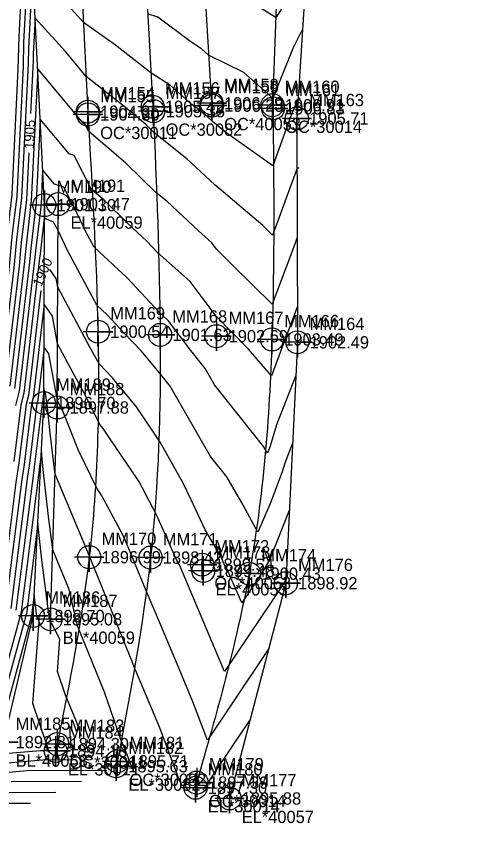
# Model space of a CAD drawing. Extents: x 1004378 to 1005103, y 553854 to 554288.
# Drawn here: x 1004990.4 to 1005086, y 553861.2 to 554030.8 of the extents above; entities that cross this region are included whole.
import ezdxf

# ---------------------------------------------------------------- set-up
doc = ezdxf.new("R2010")
doc.units = 0
for name, color, linetype in [('DTM Contours Major', 7, 'Continuous'), ('DTM Contours Major Text', 7, 'Continuous'), ('DTM Contours Minor', 7, 'Continuous'), ('Exist DTM Breakline', 7, 'Continuous'), ('Exist DTM Breakline Cogo Comment', 7, 'Continuous'), ('Exist DTM Breakline Cogo Elevation', 7, 'Continuous'), ('Exist DTM Breakline Cogo Number', 7, 'Continuous'), ('Exist DTM Breakline Cogo Point CELL', 7, 'Continuous'), ('Exist DTM Crownline', 7, 'Continuous'), ('Exist DTM Crownline Cogo Comment', 7, 'Continuous'), ('Exist DTM Crownline Cogo Elevation', 7, 'Continuous'), ('Exist DTM Crownline Cogo Number', 7, 'Continuous'), ('Exist DTM Crownline Cogo Point CELL', 7, 'Continuous'), ('Exist Roads EOP', 7, 'Continuous'), ('Exist Roads EOP Cogo Comment', 7, 'Continuous'), ('Exist Roads EOP Cogo Elevation', 7, 'Continuous'), ('Exist Roads EOP Cogo Number', 7, 'Continuous'), ('Exist Roads EOP Cogo Point CELL', 7, 'Continuous')]:
    doc.layers.add(name, color=color, linetype=linetype)

msp = doc.modelspace()

# ---------------------------------------------------------------- linework, layer by layer
at = {"layer": 'DTM Contours Major'}
for points in [[(1005047.91, 553999.99), (1005047.5, 554000.01), (1005043.02, 553987.76), (1005042.49, 553986.36), (1005040.56, 553988.28), (1005030.78, 553996.6), (1005025.09, 554001.89), (1005018.38, 554007.25), (1005016.77, 554008.82), (1005013.79, 554011.34), (1005013.15, 554011.88), (1005012.9, 554012.07), (1005004.57, 554018.62), (1005000.33, 554023.7), (1004994.19, 554030.53), (1004993.8, 554023.22), (1004993.77, 554021.82), (1004993.26, 554011.12)], [(1004992.87, 554003.13), (1004992.42, 553993.62), (1004991.37, 553984.88), (1004990.92, 553980.07), (1004988.11, 553956.08), (1004986.93, 553951.45), (1004985.68, 553941.48), (1004984.33, 553932.76), (1004981.8, 553912.85), (1004981.75, 553912.53), (1004979.52, 553904.17)], [(1005045.93, 553930.3), (1005041.91, 553920.21), (1005039.87, 553916.92), (1005036.26, 553911.52), (1005033.57, 553917.72), (1005033.17, 553918.35), (1005031.99, 553920.94), (1005028.82, 553926.38), (1005025.97, 553932.52), (1005024.26, 553936), (1005019.63, 553944.2), (1005014.83, 553951.43), (1005011.82, 553955.02), (1005009.84, 553957.4), (1005007.19, 553960.18), (1005005.29, 553963.57), (1004998.8, 553975.75), (1004998.47, 553977.56), (1004997.19, 553979.39)], [(1004995.34, 553975.11), (1004992.83, 553953.74), (1004992.37, 553951.9), (1004990.88, 553940), (1004990.26, 553936.01), (1004987.1, 553911.09), (1004987.07, 553910.91), (1004985.27, 553904.17), (1004980.32, 553886.22), (1004977.19, 553877.08)], [(1004998.72, 553897.59), (1004999.24, 553904.13), (1004997.1, 553908.23), (1004995.53, 553920.31), (1004994.71, 553927.66), (1004992.39, 553909.32), (1004992.38, 553909.29), (1004992.01, 553907.9), (1004985.46, 553884.12), (1004984.06, 553880.03), (1004983.56, 553878.58), (1004995.75, 553879.6), (1005002.27, 553879.64)], [(1005003.63, 553884.36), (1005002.66, 553887.17), (1005000.39, 553892.74), (1004998.72, 553897.59)]]:
    msp.add_lwpolyline(points, dxfattribs=at)
at = {"layer": 'DTM Contours Minor'}
for points in [[(1005048.17, 554014.12), (1005047.74, 554014.14), (1005046.29, 554010.74), (1005046.23, 554010.63), (1005042.56, 554000.44), (1005032.99, 554007.21), (1005030.3, 554009.5), (1005029.17, 554010.55), (1005026.87, 554012.38), (1005026.42, 554012.67), (1005026.07, 554012.93), (1005021.74, 554016.78), (1005017.73, 554019.38), (1005010.51, 554025), (1005004.02, 554029.64), (1004995.48, 554039.15)], [(1004991.39, 554037.31), (1004990.84, 554026.76), (1004990.69, 554020.12), (1004989.46, 553994.57), (1004988.51, 553986.65), (1004987.78, 553978.89), (1004985.27, 553957.48), (1004983.67, 553951.19), (1004982.57, 553942.36), (1004980.77, 553930.81), (1004978.63, 553913.91), (1004978.56, 553913.5), (1004974.48, 553898.21), (1004972.11, 553889.58), (1004965.54, 553870.4), (1004956.56, 553865.52), (1004952.9, 553863.53)], [(1004992.42, 554036.73), (1004991.83, 554025.58), (1004991.72, 554020.69), (1004990.45, 553994.25), (1004989.47, 553986.06), (1004988.82, 553979.28), (1004986.22, 553957.01), (1004984.76, 553951.28), (1004983.61, 553942.07), (1004981.96, 553931.46), (1004979.69, 553913.56), (1004979.63, 553913.17), (1004975.83, 553898.95), (1004973.13, 553889.16), (1004965.67, 553867.39), (1004961.09, 553864.9), (1004956.41, 553862.35)], [(1004993.44, 554036.15), (1004992.81, 554024.4), (1004992.74, 554021.25), (1004991.43, 553993.93), (1004990.42, 553985.47), (1004989.87, 553979.68), (1004987.16, 553956.55), (1004985.84, 553951.37), (1004984.64, 553941.77), (1004983.15, 553932.11), (1004980.75, 553913.21), (1004980.69, 553912.85), (1004977.18, 553899.7), (1004974.16, 553888.74), (1004965.81, 553864.38), (1004965.62, 553864.28), (1004959.92, 553861.18)], [(1005045.03, 554033.43), (1005043.18, 554030.65), (1005034.44, 554036.03)], [(1005048.63, 554028.24), (1005046.65, 554024.32), (1005042.56, 554014.24), (1005036.66, 554019.42), (1005029.51, 554022.98), (1005028.05, 554024.28), (1005025.89, 554025.68), (1005019.17, 554030.68), (1005017.07, 554031.39)], [(1005047.64, 553985.85), (1005047.53, 553985.86), (1005046.25, 553982.35), (1005042.43, 553972.28), (1005034.55, 553980.06), (1005031.13, 553983.52), (1005030.17, 553984.8), (1005027.47, 553987.22), (1005021.02, 553993.23), (1005018.75, 553995.04), (1005012.58, 554001.07), (1005005.09, 554007.41), (1005004.3, 554008.99), (1005004.05, 554009.07), (1004994.7, 554020.22), (1004993.4, 553993.3), (1004992.33, 553984.29), (1004991.96, 553980.46), (1004989.05, 553955.61)], [(1005047.56, 553971.71), (1005044.95, 553964.83), (1005042.27, 553957.75), (1005037.64, 553963.14), (1005031.01, 553969.84), (1005025.73, 553976.9), (1005019.12, 553982.83), (1005016.95, 553985.14), (1005013, 553988.81), (1005008.39, 553993.31), (1005005.63, 553995.64), (1005002.16, 554002.55), (1005001.09, 554002.9), (1004995.2, 554009.92), (1004994.39, 553992.98), (1004993.28, 553983.7), (1004993.01, 553980.86), (1004990, 553955.14)], [(1005047.25, 553957.77), (1005043.34, 553947.75), (1005042.05, 553943.43), (1005041.51, 553941.97), (1005040.74, 553943.31), (1005030.69, 553955.9), (1005028.77, 553959.24), (1005025.85, 553962.91), (1005021.29, 553969), (1005019.49, 553970.61), (1005012.89, 553977.64), (1005006.18, 553983.88), (1005004.42, 553987.16), (1005002.85, 553990.5), (1005000.02, 553996.1), (1004998.12, 553996.74), (1004995.71, 553999.61), (1004995.38, 553992.67), (1004994.23, 553983.11), (1004994.05, 553981.25), (1004990.94, 553954.67), (1004990.19, 553951.72)], [(1005046.59, 553944.03), (1005045, 553939.97), (1005044.48, 553938.21), (1005042.13, 553931.91), (1005039.54, 553925.94), (1005036.19, 553932.02), (1005033.22, 553937.19), (1005029.91, 553941.34), (1005021.69, 553955.63), (1005019.79, 553958.02), (1005015.86, 553962.72), (1005012.33, 553966.42), (1005008.83, 553970.14), (1005006.72, 553972.11), (1005000.77, 553983.24), (1004998.86, 553987.29), (1004997.91, 553989), (1004996.05, 553989.78), (1004995.18, 553982.52), (1004995.1, 553981.65), (1004991.89, 553954.21), (1004991.28, 553951.81), (1004989.84, 553940.3)], [(1005045.28, 553916.57), (1005044.99, 553915.86), (1005044.85, 553915.62), (1005032.75, 553897.54), (1005031.76, 553899.83), (1005025.62, 553914.47), (1005023.57, 553919.26), (1005023.12, 553919.99), (1005019.25, 553928.69), (1005018.99, 553929.26), (1005018.84, 553929.58), (1005015.27, 553936.32), (1005009.26, 553945.18), (1005008.05, 553947), (1005007.37, 553947.81), (1005004.37, 553953.85), (1005002.18, 553957.77), (1004998.75, 553964.22), (1004997.71, 553969.88), (1004996.01, 553972.31), (1004993.78, 553953.27), (1004993.45, 553951.99), (1004991.92, 553939.71), (1004991.44, 553936.66), (1004988.15, 553910.74)], [(1005041.74, 553902.23), (1005034.79, 553891.83), (1005029.24, 553883.56), (1005026.32, 553891.42), (1005023.5, 553898.08), (1005019.77, 553906.99), (1005016.63, 553914.3), (1005014.02, 553920.76), (1005012.14, 553925.08), (1005007.74, 553933.28), (1005007.44, 553933.84), (1005006.83, 553934.74), (1005003, 553942.51), (1004999.72, 553950.72), (1004999.31, 553951.56), (1004999.07, 553951.98), (1004998.7, 553952.68), (1004996.95, 553962.2), (1004995.99, 553963.57), (1004994.72, 553952.8), (1004994.54, 553952.08), (1004992.96, 553939.41), (1004992.63, 553937.3), (1004989.21, 553910.38)], [(1005023.94, 553874.7), (1005023.47, 553875.69), (1005023.36, 553875.95), (1005019.59, 553886.12), (1005014.13, 553899.01), (1005013.92, 553899.6), (1005013.73, 553900.09), (1005006.71, 553917.34), (1005005.31, 553920.82), (1005005.29, 553920.87), (1005005.22, 553921), (1005002.78, 553926.86), (1004998.26, 553937.74), (1004998.23, 553937.9), (1004998.21, 553938.13), (1004997.27, 553946.07), (1004996.66, 553951.96), (1004996.19, 553954.51), (1004995.96, 553954.83), (1004995.67, 553952.33), (1004995.63, 553952.16), (1004994, 553939.12), (1004993.82, 553937.95), (1004990.27, 553910.03)], [(1005014.22, 553877.33), (1005014.09, 553877.59), (1005013.7, 553878.53), (1005012.86, 553880.82), (1005011.63, 553883.71), (1005008.29, 553893.39), (1005005.05, 553901.35), (1005002.81, 553906.87), (1005001.11, 553914.27), (1004997.76, 553922.33), (1004996.88, 553929.11), (1004995.83, 553938.64), (1004995.65, 553940.13), (1004995.45, 553942.11), (1004995.03, 553938.82), (1004995, 553938.6), (1004991.33, 553909.68), (1004991.32, 553909.61), (1004990.66, 553907.15), (1004984.43, 553884.54), (1004982.39, 553878.59), (1004981.67, 553876.48), (1004992.54, 553877.39), (1005008.76, 553877.47)], [(1004996.93, 553881.65), (1004996.51, 553882.87), (1004993.7, 553891.03), (1004995.03, 553907.77), (1004994.53, 553908.72), (1004994.17, 553911.51), (1004993.98, 553913.22), (1004993.44, 553908.97), (1004993.44, 553908.96), (1004993.36, 553908.64), (1004986.49, 553883.7), (1004985.72, 553881.48), (1004985.45, 553880.68), (1004996.93, 553881.65)], [(1005037.97, 553887.83), (1005037.41, 553886.99), (1005035.67, 553884.41), (1005028.79, 553874.13), (1005028.29, 553873.45)], [(1004989.33, 553875.18), (1005003.59, 553875.25)], [(1004986.12, 553872.96), (1004998.41, 553873.03)], [(1005034.2, 553873.44), (1005033.23, 553871.99), (1005033.17, 553871.92)], [(1004982.91, 553870.75), (1004993.24, 553870.8)]]:
    msp.add_lwpolyline(points, dxfattribs=at)
at = {"layer": 'Exist DTM Breakline'}
for p, q in [((1005027.5, 554055.67), (1005030.12, 554013.17)), ((1005030.12, 554013.17), (1005030.18, 554012.7)), ((1005028.18, 553919.3), (1005028.42, 553918.04))]:
    msp.add_line(p, q, dxfattribs=at)
for points in [[(1005086.04, 554233.62), (1005066.81, 554200.26), (1005058.41, 554172.31), (1005052.46, 554140.65), (1005052.44, 554096.34), (1005050.24, 554053.66), (1005047.48, 554010.1), (1005047.57, 553964.54), (1005045.23, 553915.52), (1005033.75, 553871.73)], [(1004987.71, 553883.19), (1004993.76, 553908.86), (1004995.96, 553952.19), (1004996.06, 553992.45), (1004993.93, 554035.88), (1004994.31, 554070.39), (1004993.03, 554080.74), (1004990.27, 554106.2), (1004991.44, 554130.88), (1004994.66, 554165), (1004997.71, 554181.71), (1005005.11, 554206.99)], [(1004997.31, 553908.19), (1004998.69, 553951.28), (1004998.88, 553992.66)]]:
    msp.add_lwpolyline(points, dxfattribs=at)
at = {"layer": 'Exist DTM Breakline Cogo Point CELL'}
for points in [[(1005030.12, 554016.17), (1005030.12, 554010.17), (1005030.12, 554013.17), (1005033.12, 554013.17), (1005027.12, 554013.17)], [(1005030.18, 554015.7), (1005030.18, 554009.7), (1005030.18, 554012.7), (1005033.18, 554012.7), (1005027.18, 554012.7)], [(1005047.48, 554013.1), (1005047.48, 554007.1), (1005047.48, 554010.1), (1005050.48, 554010.1), (1005044.48, 554010.1)], [(1004996.06, 553995.45), (1004996.06, 553989.45), (1004996.06, 553992.45), (1004999.06, 553992.45), (1004993.06, 553992.45)], [(1004998.88, 553995.66), (1004998.88, 553989.66), (1004998.88, 553992.66), (1005001.88, 553992.66), (1004995.88, 553992.66)], [(1005031.08, 553968.79), (1005031.08, 553962.79), (1005031.08, 553965.79), (1005034.08, 553965.79), (1005028.08, 553965.79)], [(1005047.57, 553967.54), (1005047.57, 553961.54), (1005047.57, 553964.54), (1005050.57, 553964.54), (1005044.57, 553964.54)], [(1004995.96, 553955.19), (1004995.96, 553949.19), (1004995.96, 553952.19), (1004998.96, 553952.19), (1004992.96, 553952.19)], [(1004998.69, 553954.28), (1004998.69, 553948.28), (1004998.69, 553951.28), (1005001.69, 553951.28), (1004995.69, 553951.28)], [(1005028.18, 553922.3), (1005028.18, 553916.3), (1005028.18, 553919.3), (1005031.18, 553919.3), (1005025.18, 553919.3)], [(1005028.42, 553921.04), (1005028.42, 553915.04), (1005028.42, 553918.04), (1005031.42, 553918.04), (1005025.42, 553918.04)], [(1005045.23, 553918.52), (1005045.23, 553912.52), (1005045.23, 553915.52), (1005048.23, 553915.52), (1005042.23, 553915.52)], [(1004993.76, 553911.86), (1004993.76, 553905.86), (1004993.76, 553908.86), (1004996.76, 553908.86), (1004990.76, 553908.86)], [(1004997.31, 553911.19), (1004997.31, 553905.19), (1004997.31, 553908.19), (1005000.31, 553908.19), (1004994.31, 553908.19)], [(1004987.71, 553886.19), (1004987.71, 553880.19), (1004987.71, 553883.19), (1004990.71, 553883.19), (1004984.71, 553883.19)], [(1005033.75, 553874.73), (1005033.75, 553868.73), (1005033.75, 553871.73), (1005036.75, 553871.73), (1005030.75, 553871.73)]]:
    msp.add_lwpolyline(points, dxfattribs=at)
for centre in [(1005030.12, 554013.17), (1005030.18, 554012.7), (1005047.48, 554010.1), (1004996.06, 553992.45), (1004998.88, 553992.66), (1005031.08, 553965.79), (1005047.57, 553964.54), (1004995.96, 553952.19), (1004998.69, 553951.28), (1005028.18, 553919.3), (1005028.42, 553918.04), (1005045.23, 553915.52), (1004993.76, 553908.86), (1004997.31, 553908.19), (1005033.75, 553871.73)]:
    msp.add_circle(centre, 2.34, dxfattribs=at)
at = {"layer": 'Exist DTM Crownline'}
for p, q in [((1005015.77, 554055.21), (1005018.11, 554012.47)), ((1005018.11, 554012.47), (1005018.25, 554011.57)), ((1005010.91, 553879.28), (1005010.66, 553878.29))]:
    msp.add_line(p, q, dxfattribs=at)
msp.add_spline([(1005018.25, 554011.57), (1005019.63, 553966.05), (1005017.68, 553920.74), (1005010.91, 553879.28)], degree=3, dxfattribs=at)
at = {"layer": 'Exist DTM Crownline Cogo Point CELL'}
for points in [[(1005018.11, 554015.47), (1005018.11, 554009.47), (1005018.11, 554012.47), (1005021.11, 554012.47), (1005015.11, 554012.47)], [(1005018.25, 554014.57), (1005018.25, 554008.57), (1005018.25, 554011.57), (1005021.25, 554011.57), (1005015.25, 554011.57)], [(1005019.63, 553969.05), (1005019.63, 553963.05), (1005019.63, 553966.05), (1005022.63, 553966.05), (1005016.63, 553966.05)], [(1005017.68, 553923.74), (1005017.68, 553917.74), (1005017.68, 553920.74), (1005020.68, 553920.74), (1005014.68, 553920.74)], [(1005010.91, 553882.28), (1005010.91, 553876.28), (1005010.91, 553879.28), (1005013.91, 553879.28), (1005007.91, 553879.28)], [(1005010.66, 553881.29), (1005010.66, 553875.29), (1005010.66, 553878.29), (1005013.66, 553878.29), (1005007.66, 553878.29)]]:
    msp.add_lwpolyline(points, dxfattribs=at)
for centre in [(1005018.11, 554012.47), (1005018.25, 554011.57), (1005019.63, 553966.05), (1005017.68, 553920.74), (1005010.91, 553879.28), (1005010.66, 553878.29)]:
    msp.add_circle(centre, 2.34, dxfattribs=at)
at = {"layer": 'Exist Roads EOP'}
for p, q in [((1005002.79, 554054.52), (1005004.92, 554011.46)), ((1005044.11, 554055.39), (1005042.51, 554012.79)), ((1005042.51, 554012.79), (1005042.61, 554012.15)), ((1005004.92, 554011.46), (1005004.93, 554010.9)), ((1004998.69, 553882.79), (1004998.36, 553881.41)), ((1005027.08, 553874.96), (1005026.83, 553873.91))]:
    msp.add_line(p, q, dxfattribs=at)
for points in [[(1005042.61, 554012.15), (1005042.4, 553965.12), (1005037.76, 553917.47), (1005027.08, 553874.96)], [(1005004.93, 554010.9), (1005006.97, 553966.7), (1005005.2, 553920.82), (1004998.69, 553882.79)]]:
    msp.add_spline(points, degree=3, dxfattribs=at)
at = {"layer": 'Exist Roads EOP Cogo Point CELL'}
for points in [[(1005042.51, 554015.79), (1005042.51, 554009.79), (1005042.51, 554012.79), (1005045.51, 554012.79), (1005039.51, 554012.79)], [(1005004.92, 554014.46), (1005004.92, 554008.46), (1005004.92, 554011.46), (1005007.92, 554011.46), (1005001.92, 554011.46)], [(1005004.93, 554013.9), (1005004.93, 554007.9), (1005004.93, 554010.9), (1005007.93, 554010.9), (1005001.93, 554010.9)], [(1005042.61, 554015.15), (1005042.61, 554009.15), (1005042.61, 554012.15), (1005045.61, 554012.15), (1005039.61, 554012.15)], [(1005006.97, 553969.7), (1005006.97, 553963.7), (1005006.97, 553966.7), (1005009.97, 553966.7), (1005003.97, 553966.7)], [(1005042.4, 553968.12), (1005042.4, 553962.12), (1005042.4, 553965.12), (1005045.4, 553965.12), (1005039.4, 553965.12)], [(1005005.2, 553923.82), (1005005.2, 553917.82), (1005005.2, 553920.82), (1005008.2, 553920.82), (1005002.2, 553920.82)], [(1005037.76, 553920.47), (1005037.76, 553914.47), (1005037.76, 553917.47), (1005040.76, 553917.47), (1005034.76, 553917.47)], [(1004998.69, 553885.79), (1004998.69, 553879.79), (1004998.69, 553882.79), (1005001.69, 553882.79), (1004995.69, 553882.79)], [(1004998.36, 553884.41), (1004998.36, 553878.41), (1004998.36, 553881.41), (1005001.36, 553881.41), (1004995.36, 553881.41)], [(1005026.83, 553876.91), (1005026.83, 553870.91), (1005026.83, 553873.91), (1005029.83, 553873.91), (1005023.83, 553873.91)], [(1005027.08, 553877.96), (1005027.08, 553871.96), (1005027.08, 553874.96), (1005030.08, 553874.96), (1005024.08, 553874.96)]]:
    msp.add_lwpolyline(points, dxfattribs=at)
for centre in [(1005004.92, 554011.46), (1005042.51, 554012.79), (1005042.61, 554012.15), (1005004.93, 554010.9), (1005006.97, 553966.7), (1005042.4, 553965.12), (1005005.2, 553920.82), (1005037.76, 553917.47), (1004998.69, 553882.79), (1004998.36, 553881.41), (1005027.08, 553874.96), (1005026.83, 553873.91)]:
    msp.add_circle(centre, 2.34, dxfattribs=at)

# ---------------------------------------------------------------- texts
at = {"layer": 'DTM Contours Major Text'}
for s, rotation, p in [('1905', 87.2516, (1004993.91, 554003.83)), ('1900', 66.608, (1004995.43, 553975.7)), ('1895', 253.993, (1005004.88, 553883.99))]:
    msp.add_text(s, height=2, rotation=rotation, dxfattribs=at).set_placement(p)
at = {"layer": 'Exist DTM Breakline Cogo Comment'}
for s, p in [('OC*40053', (1005032.68, 554007.7)), ('EL*40059', (1005001.38, 553987.66)), ('OC*40053', (1005030.68, 553914.3)), ('EL*40053', (1005030.92, 553913.04)), ('BL*40059', (1004999.81, 553903.19)), ('BL*40058', (1004990.21, 553878.19)), ('EL*40057', (1005036.25, 553866.73))]:
    msp.add_text(s, height=2.5, dxfattribs=at).set_placement(p)
at = {"layer": 'Exist DTM Breakline Cogo Elevation'}
for s, p in [('1906.29', (1005032.62, 554011.92)), ('1906.25', (1005032.68, 554011.45)), ('1905.71', (1005049.98, 554008.85)), ('1901.30', (1004998.56, 553991.2)), ('1901.47', (1005001.38, 553991.41)), ('1902.69', (1005033.58, 553964.54)), ('1902.49', (1005050.07, 553963.29)), ('1896.70', (1004998.46, 553950.94)), ('1897.88', (1005001.19, 553950.03)), ('1899.54', (1005030.68, 553918.05)), ('1899.48', (1005030.92, 553916.79)), ('1898.92', (1005047.73, 553914.27)), ('1893.70', (1004996.26, 553907.61)), ('1895.08', (1004999.81, 553906.94)), ('1892.81', (1004990.21, 553881.94)), ('1895.88', (1005036.25, 553870.48))]:
    msp.add_text(s, height=2.5, dxfattribs=at).set_placement(p)
at = {"layer": 'Exist DTM Breakline Cogo Number'}
for s, p in [('MM158', (1005032.62, 554015.67)), ('MM159', (1005032.68, 554015.2)), ('MM163', (1005049.98, 554012.6)), ('MM190', (1004998.56, 553994.95)), ('MM191', (1005001.38, 553995.16)), ('MM167', (1005033.58, 553968.29)), ('MM164', (1005050.07, 553967.04)), ('MM189', (1004998.46, 553954.69)), ('MM188', (1005001.19, 553953.78)), ('MM172', (1005030.68, 553921.8)), ('MM173', (1005030.92, 553920.54)), ('MM176', (1005047.73, 553918.02)), ('MM186', (1004996.26, 553911.36)), ('MM187', (1004999.81, 553910.69)), ('MM185', (1004990.21, 553885.69)), ('MM177', (1005036.25, 553874.23))]:
    msp.add_text(s, height=2.5, dxfattribs=at).set_placement(p)
at = {"layer": 'Exist DTM Crownline Cogo Comment'}
for s, p in [('OC*30082', (1005020.75, 554006.57)), ('OC*30082', (1005013.41, 553874.28)), ('EL*30082', (1005013.16, 553873.29))]:
    msp.add_text(s, height=2.5, dxfattribs=at).set_placement(p)
at = {"layer": 'Exist DTM Crownline Cogo Elevation'}
for s, p in [('1905.42', (1005020.61, 554011.22)), ('1905.35', (1005020.75, 554010.32)), ('1901.63', (1005022.13, 553964.8)), ('1898.42', (1005020.18, 553919.49)), ('1895.71', (1005013.41, 553878.03)), ('1895.63', (1005013.16, 553877.04))]:
    msp.add_text(s, height=2.5, dxfattribs=at).set_placement(p)
at = {"layer": 'Exist DTM Crownline Cogo Number'}
for s, p in [('MM156', (1005020.61, 554014.97)), ('MM157', (1005020.75, 554014.07)), ('MM168', (1005022.13, 553968.55)), ('MM171', (1005020.18, 553923.24)), ('MM182', (1005013.16, 553880.79)), ('MM181', (1005013.41, 553881.78))]:
    msp.add_text(s, height=2.5, dxfattribs=at).set_placement(p)
at = {"layer": 'Exist Roads EOP Cogo Comment'}
for s, p in [('OC*30014', (1005045.11, 554007.15)), ('OC*30011', (1005007.43, 554005.9)), ('OC*30011', (1005001.19, 553877.79)), ('EL*30011', (1005000.86, 553876.41)), ('EL*30014', (1005029.33, 553868.91)), ('OC*30014', (1005029.58, 553869.96))]:
    msp.add_text(s, height=2.5, dxfattribs=at).set_placement(p)
at = {"layer": 'Exist Roads EOP Cogo Elevation'}
for s, p in [('1906.91', (1005045.01, 554011.54)), ('1904.35', (1005007.42, 554010.21)), ('1904.30', (1005007.43, 554009.65)), ('1906.83', (1005045.11, 554010.9)), ('1900.54', (1005009.47, 553965.45)), ('1903.49', (1005044.9, 553963.87)), ('1896.99', (1005007.7, 553919.57)), ('1900.43', (1005040.26, 553916.22)), ('1894.30', (1005001.19, 553881.54)), ('1894.18', (1005000.86, 553880.16)), ('1897.30', (1005029.33, 553872.66)), ('1897.39', (1005029.58, 553873.71))]:
    msp.add_text(s, height=2.5, dxfattribs=at).set_placement(p)
at = {"layer": 'Exist Roads EOP Cogo Number'}
for s, p in [('MM160', (1005045.01, 554015.29)), ('MM161', (1005045.11, 554014.65)), ('MM154', (1005007.42, 554013.96)), ('MM155', (1005007.43, 554013.4)), ('MM169', (1005009.47, 553969.2)), ('MM166', (1005044.9, 553967.62)), ('MM170', (1005007.7, 553923.32)), ('MM174', (1005040.26, 553919.97)), ('MM183', (1005001.19, 553885.29)), ('MM184', (1005000.86, 553883.91)), ('MM179', (1005029.58, 553877.46)), ('MM180', (1005029.33, 553876.41))]:
    msp.add_text(s, height=2.5, dxfattribs=at).set_placement(p)

doc.saveas('drawing.dxf')
